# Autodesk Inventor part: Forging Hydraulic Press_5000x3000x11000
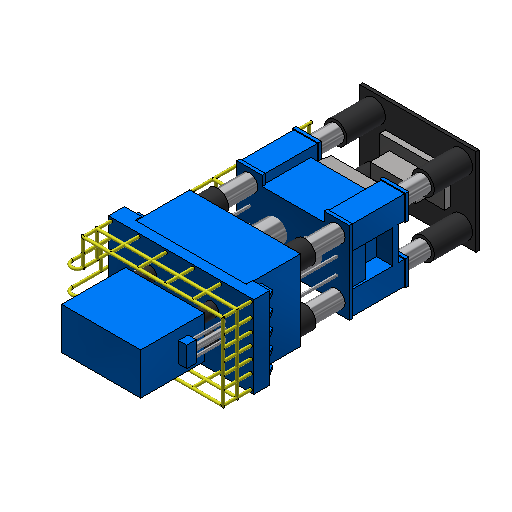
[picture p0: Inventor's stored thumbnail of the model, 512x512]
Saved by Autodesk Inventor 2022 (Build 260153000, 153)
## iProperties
RuleStatus: InUse
Created: 2013-05
Part Number: Forging Hydraulic Press_5000x3000x11000
Material: 一般
Document SubType Name: Modeling
Density: 1 g/cm^3
Appearance: Anodized - Blue
Key Parameters: Length=5000.000 mm;Width=3000.000 mm;Height=11000.000 mm;
Author: Autodesk, Inc.
Title: Forging Hydraulic Press
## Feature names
1. Extrusion1
2. Extrusion2
3. Extrusion3
4. Extrusion4
5. Extrusion5
6. Extrusion6
7. Extrusion7
8. Extrusion8
9. Extrusion9
10. Extrusion10
11. Extrusion11
12. Extrusion12
13. Extrusion13
14. Extrusion15
15. Extrusion16
16. Extrusion17
17. Extrusion18
18. Extrusion19
19. Extrusion20
20. Extrusion21
21. Extrusion22
22. Extrusion23
23. Extrusion24
24. Extrusion25
25. Extrusion26
26. Extrusion27
27. Mirror1
28. Extrusion28
29. Extrusion29
30. Extrusion30
31. Extrusion31
32. Extrusion32
33. Extrusion33
34. Extrusion34
35. Extrusion35
36. Extrusion36
37. Extrusion37
38. Rectangular Pattern1
39. Mirror2
40. Extrusion38
41. Sweep1
42. Sweep2
43. Sweep3
44. Extrusion39
45. Extrusion40
46. Mirror3
47. Mirror4
48. Mirror5
49. Extrusion41
50. Rectangular Pattern2
## Parameters: d3 = 0, d6 = 525 mm, d8 = 0, d9 = 577.5 mm, d10 = 577.5 mm, d11 = 577.5 mm, d12 = 577.5 mm, d14 = 0, d15 = 55 mm, d16 = 0, d19 = 0, d25 = 1815 mm, d26 = 0, d28 = 0, d33 = 0, d41 = 0, d43 = 0, d45 = 0, d49 = 0, d50 = -69.7 mm, d51 = 544.5 mm, d53 = 0, d54 = 181.5 mm, d56 = 0, d57 = -69.7 mm, d59 = 0, d61 = 0, d71 = 0, d110 = 0, d127 = 0, d131 = 0, d135 = 0, d148 = 0, d151 = 0, d152 = -733.33333 mm, d156 = 0, d157 = 130.35 mm, d160 = 0, d163 = 0, d164 = 0, d167 = 130.35 mm, d170 = 198 mm, d171 = 0, d172 = 1561 mm, d173 = 472 mm, d175 = 0, d176 = 0, d177 = 609.875 mm, d183 = 0, d185 = 297 mm, d186 = 0, d189 = 132 mm, d190 = 0, d194 = 82.5 mm, d195 = 0, d201 = -5 deg, d203 = 0, d205 = 0, d207 = 0, d209 = -282 mm, d211 = 60 deg, d214 = 0, d217 = 564 mm, d250 = 937.5 mm, d257 = 805.71429 mm, d259 = 423 mm, d261 = 423 mm, d263 = 423 mm, d266 = 423 mm, d271 = 962.5 mm, d272 = 0, d273 = 402.85714 mm, d275 = 0, d276 = 0, d281 = 0, d289 = 805.71429 mm, d290 = 0, d291 = 102.14286 mm, d294 = 805.71429 mm, d295 = 0, d296 = 805.71429 mm, d297 = 0, d299 = 2128.5 mm, d302 = 1064.25 mm, d303 = 846 mm, d304 = 423 mm, d305 = 2128.5 mm, d306 = 1064.25 mm, d307 = 423 mm, d308 = 846 mm, d309 = 0, d310 = 0, d311 = 0
